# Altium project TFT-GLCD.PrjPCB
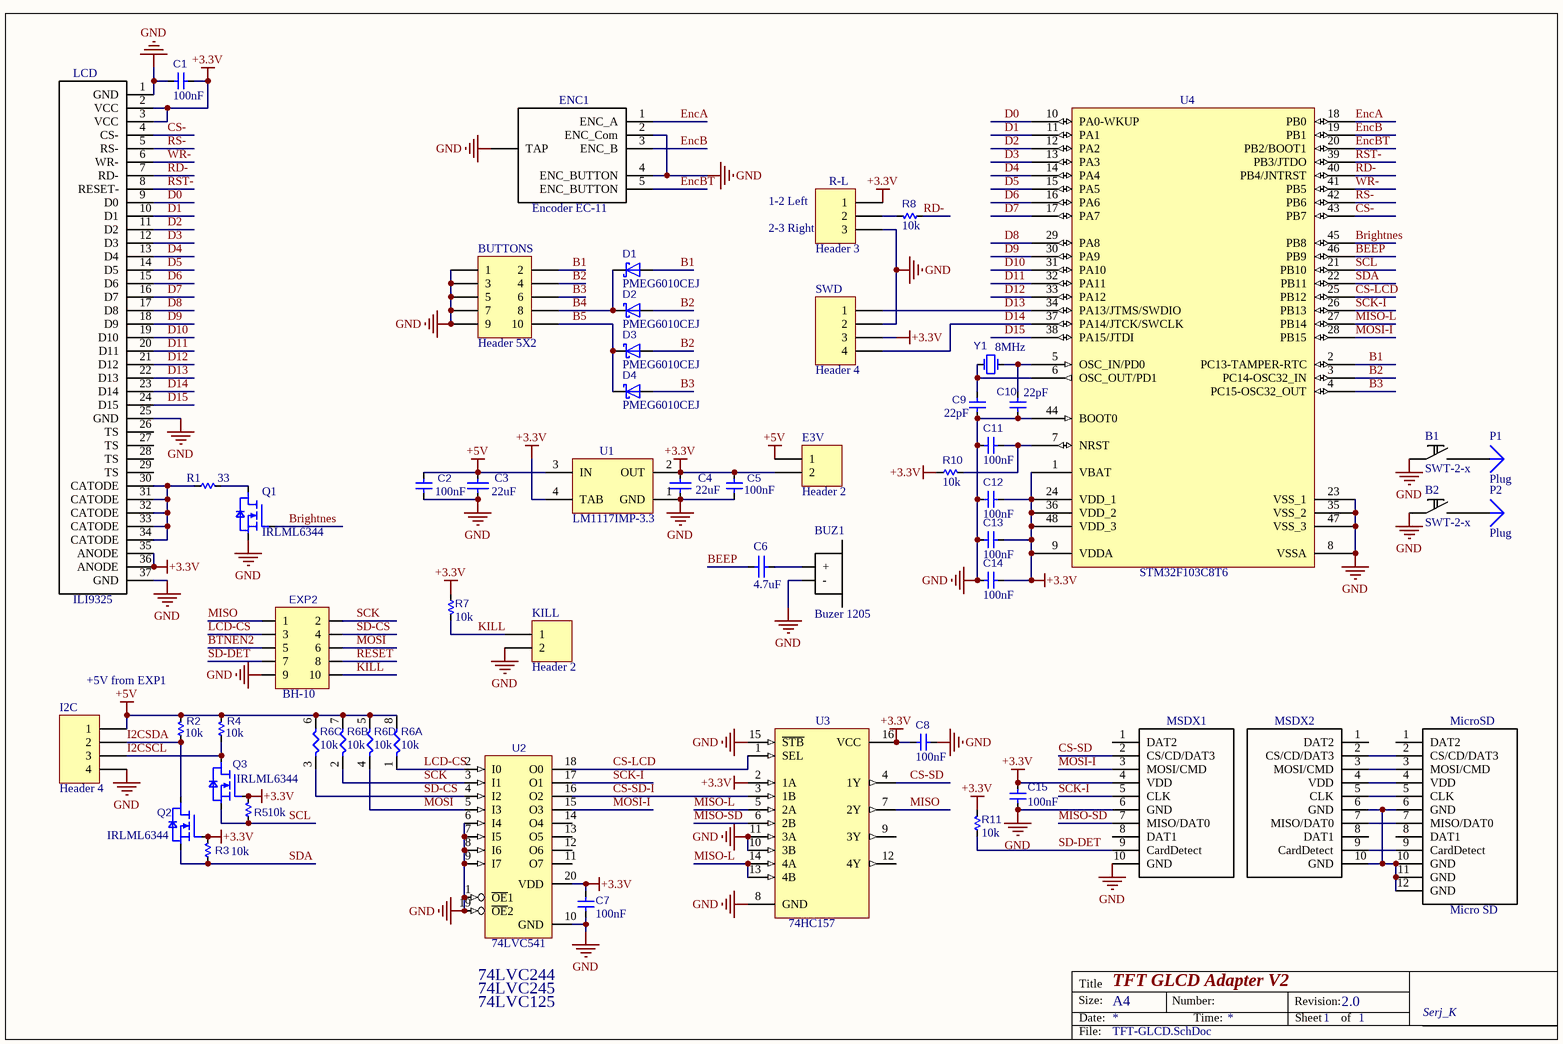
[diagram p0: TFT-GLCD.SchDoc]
1 sheet, 54 parts. Net scope: global (net labels, ports and power ports of the same name join across sheets).
Board file: TFT-GLCD.PcbDoc

## Sheet TFT-GLCD.SchDoc: TFT GLCD Adapter V2
size A4; Engineer: Serj_K; Revision: 2.0; SheetNumber: 1; SheetTotal: 1

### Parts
B1  SWT-2-x  [SWT-2-x]
B2  SWT-2-x  [SWT-2-x]
BUTTONS  Header 5X2  [HDR2X5]
BUZ1  Buzer 1205  [Buzer_12xx]
C1  value 100nF  [C0603_Samsung]  (hidden comment: Cap)
C2  value 100nF  [C0603_Samsung]  (hidden comment: Cap)
C3  value 22uF  [C1206_Murata]  (hidden comment: Cap)
C4  value 22uF  [C1206_Murata]  (hidden comment: Cap)
C5  value 100nF  [C0603_Samsung]  (hidden comment: Cap)
C6  value 4.7uF  [C1206_Murata]  (hidden comment: Cap)
C7  value 100nF  [C0603_Samsung]  (hidden comment: Cap)
C8  value 100nF  [C0603_Samsung]  (hidden comment: Cap)
C9  value 22pF  [C0603_Samsung]  (hidden comment: Cap)
C10  value 22pF  [C0603_Samsung]  (hidden comment: Cap)
C11  value 100nF  [C0603_Samsung]  (hidden comment: Cap)
C12  value 100nF  [C0603_Samsung]  (hidden comment: Cap)
C13  value 100nF  [C0603_Samsung]  (hidden comment: Cap)
C14  value 100nF  [C0603_Samsung]  (hidden comment: Cap)
C15  value 100nF  [C0603_Samsung]  (hidden comment: Cap)
D1  Part Label: PMEG6010CEJ  [SOD323FL_NXP]  (hidden comment: D_Schottky)
D2  Part Label: PMEG6010CEJ  [SOD323FL_NXP]  (hidden comment: D_Schottky)
D3  Part Label: PMEG6010CEJ  [SOD323FL_NXP]  (hidden comment: D_Schottky)
D4  Part Label: PMEG6010CEJ  [SOD323FL_NXP]  (hidden comment: D_Schottky)
E3V  Header 2  [HDR1X2]
ENC1  Encoder EC-11  [Encoder_bot]
EXP2  HEADER 2X5_BH10  [BH-10]  (value not drawn)
I2C  Header 4  [HDR1X4]
KILL  Header 2  [HDR1X2]
LCD  ILI9325  [LCD_ILI9325-37pin]
MicroSD  Micro SD  [TFP09-2-12B]
MSDX1  CrossPCB-MicroSD  [CrossPCB-MicroSD-MB]  (value not drawn)
MSDX2  CrossPCB-MicroSD  [CrossPCB-MicroSD-SD]  (value not drawn)
P1  Plug  [PLS-1x1]
P2  Plug  [PLS-1x1]
Q1  IRLML6344  [SOT23-3_IR]
Q2  IRLML6344  [SOT23-3_IR]
Q3  IRLML6344  [SOT23-3_IR]
R1  value 33  [R0805_UniOhm]  (hidden comment: R)
R2  value 10k  [R0603_UniOhm]  (hidden comment: R)
R3  value 10k  [R0603_UniOhm]  (hidden comment: R)
R4  value 10k  [R0603_UniOhm]  (hidden comment: R)
R5  value 10k  [R0603_UniOhm]  (hidden comment: R)
R6  value 10k  [RES_Array_ROHM_MNR14]  (hidden comment: array_r_x4s)  (parts A,B,C,D of 4)
R7  value 10k  [R0603_UniOhm]  (hidden comment: R)
R8  value 10k  [R0603_UniOhm]  (hidden comment: R)
R10  value 10k  [R0603_UniOhm]  (hidden comment: R)
R11  value 10k  [R0603_UniOhm]  (hidden comment: R)
R-L  Header 3  [HDR1X3]
SWD  Header 4  [HDR1X4]
U1  LM1117IMP-3.3  [MP04A_N]
U2  Part Label: 74LVC541  [TSSOP20]  (hidden comment: LCX541)
U3  74HC157  [SO16_N]
U4  STM32F103C8T6  [LQFP48_N]
Y1  value 8MHz  [XTAL_HC-49_SS3]  (hidden comment: XTAL)

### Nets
+3.3V: C1.2 C4.2 C5.2 C7.2 C8.2 C12.2 C13.2 C14.2 C15.2 E3V.2 LCD.2(VCC) LCD.3(VCC) LCD.35(ANODE) LCD.36(ANODE) MSDX1.4(VDD) Q2.1(G) Q3.1(G) R3.2 R5.2 R7.1 R10.1 R11.2 R-L.1 SWD.3 U1.2(OUT) U1.4(TAB) U2.20(VDD) U3.2(1A) U3.16(VCC) U4.1(VBAT) U4.9(VDDA) U4.24(VDD_1) U4.36(VDD_2) U4.48(VDD_3)
+5V: C2.2 C3.2 E3V.1 I2C.1 R2.2 R4.2 R6.5 R6.6 R6.7 R6.8 U1.3(IN)
GND: B1.1 B2.1 BUTTONS.1 BUTTONS.3 BUTTONS.5 BUTTONS.7 BUTTONS.9 BUZ1.2(-) C1.1 C2.1 C3.1 C4.1 C5.1 C7.1 C8.1 C9.1 C10.1 C11.1 C12.1 C13.1 C14.1 C15.1 ENC1.0(TAP) ENC1.2(ENC_Com) ENC1.4(ENC_BUTTON) EXP2.9 I2C.4 KILL.2 LCD.1(GND) LCD.25(GND) LCD.37(GND) MSDX1.6(GND) MSDX1.10(GND) Q1.2(S) R-L.3 SWD.2 U1.1(GND) U2.1(~{OE}1) U2.6(I4) U2.7(I5) U2.8(I6) U2.9(I7) U2.10(GND) U2.19(~{OE}2) U3.8(GND) U3.10(3B) U3.11(3A) U3.15(~{STB}) U4.8(VSSA) U4.23(VSS_1) U4.35(VSS_2) U4.44(BOOT0) U4.47(VSS_3)
B1: BUTTONS.2 D1.A U4.2(PC13-TAMPER-RTC)
B2: BUTTONS.4 D2.A D3.A U4.3(PC14-OSC32_IN)
B3: BUTTONS.6 D4.A U4.4(PC15-OSC32_OUT)
B4: BUTTONS.8 D1.C D2.C
B5: BUTTONS.10 D3.C D4.C
BEEP: C6.2 U4.46(PB9)
Brightnes: Q1.1(G) U4.45(PB8)
BTNEN2: EXP2.5
CS-: LCD.4(CS-) U4.43(PB7)
CS-LCD: U2.18(O0) U3.1(SEL) U4.25(PB12)
CS-SD: MSDX1.2(CS/CD/DAT3) U3.4(1Y)
CS-SD-I: U2.16(O2) U3.3(1B)
D0: LCD.9(D0) U4.10(PA0-WKUP)
D1: LCD.10(D1) U4.11(PA1)
D2: LCD.11(D2) U4.12(PA2)
D3: LCD.12(D3) U4.13(PA3)
D4: LCD.13(D4) U4.14(PA4)
D5: LCD.14(D5) U4.15(PA5)
D6: LCD.15(D6) U4.16(PA6)
D7: LCD.16(D7) U4.17(PA7)
D8: LCD.17(D8) U4.29(PA8)
D9: LCD.18(D9) U4.30(PA9)
D10: LCD.19(D10) U4.31(PA10)
D11: LCD.20(D11) U4.32(PA11)
D12: LCD.21(D12) U4.33(PA12)
D13: LCD.22(D13) SWD.1 U4.34(PA13/JTMS/SWDIO)
D14: LCD.23(D14) SWD.4 U4.37(PA14/JTCK/SWCLK)
D15: LCD.24(D15) U4.38(PA15/JTDI)
EncA: ENC1.1(ENC_A) U4.18(PB0)
EncB: ENC1.3(ENC_B) U4.19(PB1)
EncBT: ENC1.5(ENC_BUTTON) U4.20(PB2/BOOT1)
I2CSCL: I2C.3 Q3.3(D) R4.1
I2CSDA: I2C.2 Q2.3(D) R2.1
KILL: EXP2.10 KILL.1 R7.2
LCD-CS: EXP2.3 R6.1 U2.2(I0)
MISO: EXP2.1 U3.7(2Y)
MISO-L: U3.5(2A) U3.13(4B) U3.14(4A) U4.27(PB14)
MISO-SD: MSDX1.7(MISO/DAT0) U3.6(2B)
MOSI: EXP2.6 R6.4 U2.5(I3)
MOSI-I: MSDX1.3(MOSI/CMD) U2.15(O3) U4.28(PB15)
RD-: LCD.7(RD-) R8.1 U4.40(PB4/JNTRST)
RESET: EXP2.8
RS-: LCD.5(RS-) U4.42(PB6)
RST-: LCD.8(RESET-) U4.39(PB3/JTDO)
SCK: EXP2.2 R6.2 U2.3(I1)
SCK-I: MSDX1.5(CLK) U2.17(O1) U4.26(PB13)
SCL: Q3.2(S) R5.1 U4.21(PB10)
SD-CS: EXP2.4 R6.3 U2.4(I2)
SD-DET: EXP2.7 MSDX1.9(CardDetect) R11.1
SDA: Q2.2(S) R3.1 U4.22(PB11)
WR-: LCD.6(WR-) U4.41(PB5)
NetB1_2: B1.2 P1.1
NetB2_2: B2.2 P2.1
NetBUZ1_1: BUZ1.1(+) C6.1
NetC9_2: C9.2 U4.6(OSC_OUT/PD1) Y1.1(OSC1)
NetC10_2: C10.2 U4.5(OSC_IN/PD0) Y1.2(OSC2)
NetC11_2: C11.2 R10.2 U4.7(NRST)
NetLCD_30: LCD.30(CATODE) LCD.31(CATODE) LCD.32(CATODE) LCD.33(CATODE) LCD.34(CATODE) R1.1
NetMicroSD_2: MicroSD.2(CS/CD/DAT3) MSDX2.2(CS/CD/DAT3)
NetMicroSD_3: MicroSD.3(MOSI/CMD) MSDX2.3(MOSI/CMD)
NetMicroSD_4: MicroSD.4(VDD) MSDX2.4(VDD)
NetMicroSD_5: MicroSD.5(CLK) MSDX2.5(CLK)
NetMicroSD_6: MicroSD.6(GND) MicroSD.10(GND) MicroSD.11(GND) MicroSD.12(GND) MSDX2.6(GND) MSDX2.10(GND)
NetMicroSD_7: MicroSD.7(MISO/DAT0) MSDX2.7(MISO/DAT0)
NetMicroSD_9: MicroSD.9(CardDetect) MSDX2.9(CardDetect)
NetQ1_3: Q1.3(D) R1.2
NetR8_2: R8.2 R-L.2

Not connected (* = marked no-connect by the designer): LCD 26(TS) 27(TS) 28(TS) 29(TS); MicroSD 1(DAT2) 8(DAT1); MSDX1 1(DAT2) 8(DAT1); MSDX2 1(DAT2) 8(DAT1); U2 11(O7) 12(O6) 13(O5) 14(O4); U3 9(3Y) 12(4Y)

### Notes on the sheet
- (near R-L) 1-2 Left
- (near R-L) 2-3 Right
- +5V from EXP1
- (near U2) 74LVC244
- 74LVC245
- 74LVC125

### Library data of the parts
BUTTONS = Header 5X2: Header, 5-Pin, Dual row
BUZ1 = Buzer
C1 C2 C5 C7 C8 C11-C15 = CL10B104KB8NNNC: PartName: CL10; Part Label: C0603 100nF 10% X7R 50V; Manufacturer: Samsung Electro-Mechanics; Voltage: 50V; Tolerance: 10 %; Device: C; ShortName: C0603
C3 C4 C6 = GRM31CR71H475KA12L: PartName: GRM31; Part Label: C1206 4.7uF 10% X7R 50V; Manufacturer: muRata; Voltage: 50V; Tolerance: 10 %; Device: C; ShortName: C1206
C9 C10 = CL10C220JB8NNNC: PartName: CL10; Part Label: C0603 22pF 5% NP0 50V; Manufacturer: Samsung Electro-Mechanics; Voltage: 50V; Tolerance: 5 %; Device: C; ShortName: C0603
D1-D4 = PMEG6010CEJ,115: 60V, 1A, very low VF MEGA Schottky barrier rectifiers; Manufacturer: NXP Semiconductors; ClassName_u: Schottky SMD; Device: D
E3V KILL = Header 2: Header, 2-Pin
ENC1 = Encoder: Rotary Encoder with button
EXP2 = BH-10: IDC-10M Connector (BH-10); PartName: BH-10V; Manufacturer: Unknown; ClassName_u: Wire To Board; Device: J
I2C SWD = Header 4: Header, 4-Pin
LCD = LCD_ILI9325-37pin
MicroSD = TFP09-2-12B
MSDX1 MSDX2 = CrossPCB-MicroSD: Micro SD CrossPCB connector
Q1-Q3 = IRLML6344TRPBF: 30 V, 5.0 A, 0.029 Ohm Single N-Channel HEXFET Power MOSFET; Manufacturer: International Rectifier; Device: Q; ShortName: NMOS
R1 = 0805S8F4700T50: PartName: 0805S; Part Label: R0805 470 1% TC100 150V; Manufacturer: uniOhm; TempCo: 100 ppm; Tolerance: 1 %; ShortName: R0805
R2-R5 R7 R8 R10 R11 = 0603SAF1002T50: PartName: 0603SA; Part Label: R0603 10k 1% TC100 50V; Manufacturer: uniOhm; TempCo: 100 ppm; Tolerance: 1 %; ShortName: R0603
R6 = MNR14ERAPJ103: 4x Chip Array Convex; PartName: MNR14; Part Label: R0612 10k 5% TC200 50V; Manufacturer: ROHM; TempCo: 200 ppm; Tolerance: 5 %; ClassName_u: SMD Array; Device: R; ShortName: R0612
R-L = Header 3: Header, 3-Pin
U1 = LM1117IMP-3.3: 800mA Low-Dropout Linear Regulator; Manufacturer: National Semiconductor; CompType: LDO IC; PackageTopMarking: XYTT*N05B; PowerWise: N
U2 = 74LCX541MTC: Low Voltage Octal Buffer with 5V Tolerant Inputs and Outputs; PartName: LVC541PW; Manufacturer: Fairchild Semiconductor; ClassName_u: Logic; Device: U
U3 = 74LVQ157M: Low-Voltage Quad 2-Channel Multiplexer
U4 = STM32F103C8T6: STM32 ARM-based 32-bit MCU with 64 Kbytes Flash, 48-pin LQFP, Industrial Temperature
Y1 = KX-3HT 10.0MHZ: 10MHz Quartz HC49; PartName: KX-3HT; Manufacturer: GEYER ELECTRONIC; ClassName_u: Quartz Crystals THD; Device: Y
